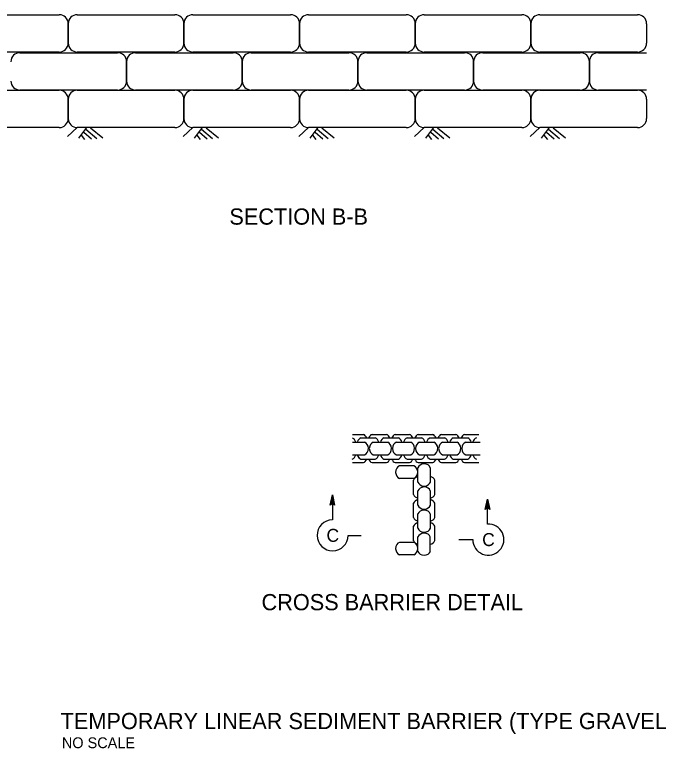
# Model space of a CAD drawing. Extents: x 6707406 to 6714471, y 1868570 to 1872341.
# Drawn here: x 6712375.3 to 6712732.5, y 1869412.9 to 1869820.3 of the extents above; entities that cross this region are included whole.
import ezdxf

# ---------------------------------------------------------------- set-up
doc = ezdxf.new("R2010")
doc.units = 0
for name, color, linetype in [('56 Stg 3 Anno', 7, 'Continuous'), ('57 Undefined', 7, 'Continuous'), ('59 Soundwall Ann', 7, 'Continuous'), ('C - SANDBAG', 7, 'Continuous'), ('G-SYMB', 7, 'Continuous'), ('G-TEXT', 7, 'Continuous')]:
    doc.layers.add(name, color=color, linetype=linetype)

msp = doc.modelspace()

# ---------------------------------------------------------------- linework, layer by layer
at = {"layer": '56 Stg 3 Anno'}
for p, q in [((6712550.31, 1869547.91), (6712551.6, 1869553.67)), ((6712551.6, 1869553.67), (6712551.6, 1869553.67)), ((6712551.6, 1869553.67), (6712552.88, 1869547.91)), ((6712551.6, 1869553.67), (6712551.6, 1869539.74)), ((6712550.65, 1869548.11), (6712551.6, 1869552.35)), ((6712551, 1869548.34), (6712551.6, 1869551.02)), ((6712551.33, 1869548.51), (6712551.6, 1869549.69)), ((6712551.6, 1869552.33), (6712552.53, 1869548.13)), ((6712551.6, 1869551.02), (6712552.2, 1869548.3)), ((6712551.6, 1869549.69), (6712551.85, 1869548.53)), ((6712636.34, 1869545.55), (6712637.62, 1869551.31)), ((6712636.68, 1869545.76), (6712637.62, 1869549.99)), ((6712637.62, 1869551.31), (6712637.62, 1869551.31)), ((6712637.62, 1869551.31), (6712638.9, 1869545.55)), ((6712637.62, 1869537.38), (6712637.62, 1869551.31)), ((6712637.63, 1869549.98), (6712638.56, 1869545.78)), ((6712551.6, 1869548.68), (6712550.31, 1869547.91)), ((6712550.31, 1869547.91), (6712550.31, 1869547.91)), ((6712552.88, 1869547.91), (6712551.6, 1869548.68)), ((6712552.88, 1869547.91), (6712552.88, 1869547.91)), ((6712637.62, 1869546.32), (6712636.34, 1869545.55)), ((6712636.34, 1869545.55), (6712636.34, 1869545.55)), ((6712637.02, 1869545.98), (6712637.62, 1869548.66)), ((6712637.36, 1869546.15), (6712637.62, 1869547.33)), ((6712637.62, 1869548.66), (6712638.22, 1869545.95)), ((6712637.62, 1869547.33), (6712637.88, 1869546.17)), ((6712638.9, 1869545.55), (6712637.62, 1869546.32)), ((6712638.9, 1869545.55), (6712638.9, 1869545.55)), ((6712560.4, 1869531.11), (6712567.53, 1869531.11)), ((6712621.83, 1869528.76), (6712629.56, 1869528.76))]:
    msp.add_line(p, q, dxfattribs=at)
for centre, start, end in [((6712551.77, 1869531.12), 91.113, 359.9585), ((6712638.15, 1869528.77), 180.1055, 93.4975)]:
    msp.add_arc(centre, 8.62, start, end, dxfattribs=at)
at = {"layer": '59 Soundwall Ann'}
for p, q in [((6712410.04, 1869757.57), (6712404.56, 1869752.69)), ((6712415.24, 1869757.53), (6712410.72, 1869751.78)), ((6712417.34, 1869757.51), (6712424.27, 1869751.81)), ((6712474.23, 1869757.57), (6712468.75, 1869752.69)), ((6712479.42, 1869757.53), (6712474.91, 1869751.78)), ((6712481.53, 1869757.51), (6712488.46, 1869751.81)), ((6712538.42, 1869757.57), (6712532.94, 1869752.69)), ((6712543.61, 1869757.53), (6712539.1, 1869751.78)), ((6712545.72, 1869757.51), (6712552.64, 1869751.81)), ((6712602.61, 1869757.57), (6712597.13, 1869752.69)), ((6712607.8, 1869757.53), (6712603.28, 1869751.78)), ((6712609.91, 1869757.51), (6712616.83, 1869751.81)), ((6712666.79, 1869757.57), (6712661.32, 1869752.69)), ((6712671.99, 1869757.53), (6712667.47, 1869751.78)), ((6712674.1, 1869757.51), (6712681.02, 1869751.81)), ((6712412.16, 1869753.43), (6712414.14, 1869751)), ((6712413.66, 1869755.08), (6712417.89, 1869751.24)), ((6712414.79, 1869756.67), (6712420.98, 1869751.57)), ((6712476.35, 1869753.43), (6712478.33, 1869751)), ((6712477.85, 1869755.08), (6712482.07, 1869751.24)), ((6712478.98, 1869756.67), (6712485.17, 1869751.57)), ((6712540.54, 1869753.43), (6712542.52, 1869751)), ((6712542.04, 1869755.08), (6712546.26, 1869751.24)), ((6712543.17, 1869756.67), (6712549.36, 1869751.57)), ((6712604.72, 1869753.43), (6712606.7, 1869751)), ((6712606.22, 1869755.08), (6712610.45, 1869751.24)), ((6712607.36, 1869756.67), (6712613.55, 1869751.57)), ((6712668.91, 1869753.43), (6712670.89, 1869751)), ((6712670.41, 1869755.08), (6712674.64, 1869751.24)), ((6712671.54, 1869756.67), (6712677.73, 1869751.57))]:
    msp.add_line(p, q, dxfattribs=at)
at = {"layer": 'C - SANDBAG'}
for p, q in [((6712562.77, 1869587.15), (6712568.81, 1869587.15)), ((6712573.63, 1869587.15), (6712581.63, 1869587.15)), ((6712573.63, 1869587.15), (6712581.63, 1869587.15)), ((6712586.45, 1869587.15), (6712594.45, 1869587.15)), ((6712599.27, 1869587.15), (6712607.27, 1869587.15)), ((6712612.09, 1869587.15), (6712620.1, 1869587.15)), ((6712624.91, 1869587.15), (6712632.92, 1869587.15)), ((6712562.77, 1869582.8), (6712569.5, 1869582.8)), ((6712567.43, 1869585.2), (6712575.44, 1869585.2)), ((6712567.43, 1869585.2), (6712575.44, 1869585.2)), ((6712574.32, 1869582.8), (6712582.32, 1869582.8)), ((6712574.32, 1869582.8), (6712582.32, 1869582.8)), ((6712580.25, 1869585.2), (6712588.26, 1869585.2)), ((6712587.14, 1869582.79), (6712595.14, 1869582.79)), ((6712593.07, 1869585.2), (6712601.08, 1869585.2)), ((6712599.96, 1869582.79), (6712607.96, 1869582.79)), ((6712605.9, 1869585.2), (6712613.9, 1869585.2)), ((6712612.78, 1869582.79), (6712620.78, 1869582.79)), ((6712618.72, 1869585.2), (6712626.72, 1869585.2)), ((6712625.6, 1869582.79), (6712633.61, 1869582.79)), ((6712562.77, 1869575.9), (6712569.5, 1869575.9)), ((6712574.32, 1869575.9), (6712582.32, 1869575.9)), ((6712574.32, 1869575.9), (6712582.32, 1869575.9)), ((6712587.14, 1869575.9), (6712595.14, 1869575.9)), ((6712599.96, 1869575.9), (6712607.96, 1869575.9)), ((6712612.78, 1869575.9), (6712620.78, 1869575.9)), ((6712625.6, 1869575.9), (6712633.61, 1869575.9)), ((6712562.77, 1869571.55), (6712568.81, 1869571.55)), ((6712567.43, 1869573.5), (6712575.44, 1869573.5)), ((6712567.43, 1869573.5), (6712575.44, 1869573.5)), ((6712573.63, 1869571.55), (6712581.63, 1869571.55)), ((6712573.63, 1869571.55), (6712581.63, 1869571.55)), ((6712580.25, 1869573.5), (6712588.26, 1869573.5)), ((6712586.45, 1869571.54), (6712594.45, 1869571.54)), ((6712593.07, 1869573.5), (6712601.08, 1869573.5)), ((6712599.27, 1869571.54), (6712607.27, 1869571.54)), ((6712605.9, 1869573.5), (6712613.9, 1869573.5)), ((6712612.09, 1869571.54), (6712620.1, 1869571.54)), ((6712618.72, 1869573.5), (6712626.72, 1869573.5)), ((6712624.91, 1869571.54), (6712632.92, 1869571.54)), ((6712596.84, 1869569.67), (6712588.83, 1869569.67)), ((6712599.08, 1869560.69), (6712599.08, 1869568.7)), ((6712605.98, 1869560.69), (6712605.98, 1869568.7)), ((6712596.84, 1869562.78), (6712588.83, 1869562.78)), ((6712596.68, 1869553.81), (6712596.68, 1869561.82)), ((6712608.38, 1869553.81), (6712608.38, 1869561.82)), ((6712599.08, 1869547.87), (6712599.08, 1869555.88)), ((6712605.98, 1869547.87), (6712605.98, 1869555.88)), ((6712596.68, 1869540.99), (6712596.68, 1869549)), ((6712608.38, 1869540.99), (6712608.38, 1869549)), ((6712599.08, 1869535.05), (6712599.08, 1869543.06)), ((6712605.98, 1869535.05), (6712605.98, 1869543.06)), ((6712596.68, 1869528.17), (6712596.68, 1869536.18)), ((6712608.38, 1869528.17), (6712608.38, 1869536.18)), ((6712599.08, 1869522.23), (6712599.08, 1869530.24)), ((6712599.08, 1869522.23), (6712599.08, 1869530.24)), ((6712605.97, 1869522.23), (6712605.97, 1869530.24)), ((6712605.97, 1869522.23), (6712605.97, 1869530.24)), ((6712596.84, 1869527.24), (6712588.83, 1869527.24)), ((6712596.84, 1869520.35), (6712588.83, 1869520.35))]:
    msp.add_line(p, q, dxfattribs=at)
for centre, major_axis, ratio, start_param, end_param in [((6712568.33, 1869583.47), (0.06, -3.75), 0.71077, 2.038051, 2.935943), ((6712574.15, 1869583.47), (0.06, -3.75), 0.711359, 3.317588, 4.221159), ((6712574.15, 1869583.47), (0.06, -3.75), 0.711359, 3.317588, 4.221159), ((6712581.15, 1869583.47), (0.06, -3.75), 0.71077, 2.038051, 2.935943), ((6712581.15, 1869583.47), (0.06, -3.75), 0.71077, 2.038051, 2.935943), ((6712586.97, 1869583.47), (0.06, -3.75), 0.711359, 3.317588, 4.221159), ((6712593.97, 1869583.47), (0.06, -3.75), 0.71077, 2.038051, 2.935943), ((6712599.79, 1869583.47), (0.06, -3.75), 0.711359, 3.317588, 4.221159), ((6712606.79, 1869583.47), (0.06, -3.75), 0.71077, 2.038051, 2.935943), ((6712612.61, 1869583.47), (0.06, -3.75), 0.711359, 3.317588, 4.221159), ((6712619.61, 1869583.47), (0.06, -3.75), 0.71077, 2.038051, 2.935943), ((6712625.44, 1869583.47), (0.06, -3.75), 0.711359, 3.317588, 4.221159), ((6712562.07, 1869581.53), (0, -3.75), 0.71077, 1.915159, 2.876513), ((6712567.96, 1869581.52), (0.06, -3.75), 0.711359, 3.317588, 4.29466), ((6712567.96, 1869581.52), (0.06, -3.75), 0.711359, 3.317588, 4.29466), ((6712568.96, 1869579.12), (0, -3.75), 0.71077, 1.662213, 2.935943), ((6712574.78, 1869579.1), (0, -3.75), 0.711359, 3.317588, 4.646994), ((6712574.78, 1869579.1), (0, -3.75), 0.711359, 3.317588, 4.646994), ((6712574.9, 1869581.53), (0, -3.75), 0.71077, 1.915159, 2.935943), ((6712574.9, 1869581.53), (0, -3.75), 0.71077, 1.915159, 2.935943), ((6712580.78, 1869581.52), (0.06, -3.75), 0.711359, 3.317588, 4.353284), ((6712581.78, 1869579.12), (0, -3.75), 0.71077, 1.662213, 2.935943), ((6712581.78, 1869579.12), (0, -3.75), 0.71077, 1.662213, 2.935943), ((6712587.6, 1869579.1), (0, -3.75), 0.711359, 3.317588, 4.646994), ((6712587.72, 1869581.53), (0, -3.75), 0.71077, 1.915159, 2.935943), ((6712593.6, 1869581.52), (0.06, -3.75), 0.711359, 3.317588, 4.353284), ((6712594.6, 1869579.12), (0, -3.75), 0.71077, 1.662213, 2.935943), ((6712600.42, 1869579.1), (0, -3.75), 0.711359, 3.317588, 4.646994), ((6712600.54, 1869581.53), (0, -3.75), 0.71077, 1.915159, 2.935943), ((6712606.42, 1869581.52), (0.06, -3.75), 0.711359, 3.317588, 4.353284), ((6712607.42, 1869579.12), (0, -3.75), 0.71077, 1.662213, 2.935943), ((6712613.24, 1869579.1), (0, -3.75), 0.711359, 3.317588, 4.646994), ((6712613.36, 1869581.53), (0, -3.75), 0.71077, 1.915159, 2.935943), ((6712619.24, 1869581.52), (0.06, -3.75), 0.711359, 3.317588, 4.353284), ((6712620.24, 1869579.12), (0, -3.75), 0.71077, 1.662213, 2.935943), ((6712626.07, 1869579.1), (0, -3.75), 0.711359, 3.317588, 4.646994), ((6712626.18, 1869581.53), (0, -3.75), 0.71077, 1.915159, 2.935943), ((6712632.06, 1869581.52), (0.06, -3.75), 0.711359, 3.317588, 4.29466), ((6712568.96, 1869579.58), (0, 3.75), 0.71077, 3.347242, 4.682592), ((6712574.78, 1869579.59), (0, 3.75), 0.711359, 1.636191, 2.965597), ((6712574.78, 1869579.59), (0, 3.75), 0.711359, 1.636191, 2.965597), ((6712581.78, 1869579.58), (0, 3.75), 0.71077, 3.347242, 4.682592), ((6712581.78, 1869579.58), (0, 3.75), 0.71077, 3.347242, 4.682592), ((6712587.6, 1869579.59), (0, 3.75), 0.711359, 1.636191, 2.965597), ((6712594.6, 1869579.58), (0, 3.75), 0.71077, 3.347242, 4.682592), ((6712600.42, 1869579.59), (0, 3.75), 0.711359, 1.636191, 2.965597), ((6712607.42, 1869579.58), (0, 3.75), 0.71077, 3.347242, 4.682592), ((6712613.24, 1869579.59), (0, 3.75), 0.711359, 1.636191, 2.965597), ((6712620.24, 1869579.57), (0, 3.75), 0.71077, 3.347242, 4.682592), ((6712626.07, 1869579.59), (0, 3.75), 0.711359, 1.636191, 2.965597), ((6712562.07, 1869577.17), (0, 3.75), 0.71077, 3.347242, 4.368026), ((6712567.96, 1869577.18), (0.06, 3.75), 0.711359, 1.929645, 2.965597), ((6712567.96, 1869577.18), (0.06, 3.75), 0.711359, 1.988526, 2.965597), ((6712574.9, 1869577.17), (0, 3.75), 0.71077, 3.347242, 4.368026), ((6712574.9, 1869577.17), (0, 3.75), 0.71077, 3.347242, 4.368026), ((6712580.78, 1869577.18), (0.06, 3.75), 0.711359, 1.929645, 2.965597), ((6712587.72, 1869577.17), (0, 3.75), 0.71077, 3.347242, 4.368026), ((6712593.6, 1869577.18), (0.06, 3.75), 0.711359, 1.929645, 2.965597), ((6712600.54, 1869577.17), (0, 3.75), 0.71077, 3.347242, 4.368026), ((6712606.42, 1869577.18), (0.06, 3.75), 0.711359, 1.929645, 2.965597), ((6712613.36, 1869577.17), (0, 3.75), 0.71077, 3.347242, 4.368026), ((6712619.24, 1869577.18), (0.06, 3.75), 0.711359, 1.929645, 2.965597), ((6712626.18, 1869577.17), (0, 3.75), 0.71077, 3.347242, 4.368026), ((6712632.06, 1869577.18), (0.06, 3.75), 0.711359, 1.929645, 2.965597), ((6712568.33, 1869575.23), (0.06, 3.75), 0.71077, 3.347242, 4.244863), ((6712574.15, 1869575.23), (0.06, 3.75), 0.711359, 2.062027, 2.965597), ((6712574.15, 1869575.23), (0.06, 3.75), 0.711359, 2.062027, 2.965597), ((6712581.15, 1869575.23), (0.06, 3.75), 0.71077, 3.347242, 4.244863), ((6712581.15, 1869575.23), (0.06, 3.75), 0.71077, 3.347242, 4.244863), ((6712586.97, 1869575.23), (0.06, 3.75), 0.711359, 2.062027, 2.965597), ((6712593.97, 1869575.23), (0.06, 3.75), 0.71077, 3.347242, 4.244863), ((6712599.79, 1869575.23), (0.06, 3.75), 0.711359, 2.062027, 2.965597), ((6712602.76, 1869568.16), (3.75, 0), 0.71077, 1.662213, 2.935943), ((6712602.3, 1869568.16), (-3.75, 0), 0.71077, 3.347242, 4.682592), ((6712606.79, 1869575.23), (0.06, 3.75), 0.71077, 3.347242, 4.244863), ((6712612.61, 1869575.23), (0.06, 3.75), 0.711359, 2.062027, 2.965597), ((6712619.61, 1869575.22), (0.06, 3.75), 0.71077, 3.347242, 4.244863), ((6712625.44, 1869575.23), (0.06, 3.75), 0.711359, 2.062027, 2.965597), ((6712589.37, 1869566), (0, -3.75), 0.71077, 3.347242, 4.682592), ((6712589.37, 1869566.45), (0, 3.75), 0.71077, 1.662213, 2.935943), ((6712596.37, 1869565.98), (0, -3.75), 0.711359, 1.636191, 2.965597), ((6712596.37, 1869566.47), (0, 3.75), 0.711359, 3.317588, 4.646994), ((6712600.35, 1869561.27), (3.75, 0), 0.71077, 1.915159, 2.935943), ((6712604.71, 1869561.27), (-3.75, 0), 0.71077, 3.347242, 4.368026), ((6712602.78, 1869561.16), (3.75, 0), 0.711359, 3.317588, 4.646994), ((6712602.76, 1869555.33), (3.75, 0), 0.71077, 1.662213, 2.935943), ((6712602.3, 1869555.33), (-3.75, 0), 0.71077, 3.347242, 4.682592), ((6712602.29, 1869561.16), (-3.75, 0), 0.711359, 1.636191, 2.965597), ((6712600.36, 1869554.34), (3.75, 0.06), 0.711359, 3.317588, 4.353284), ((6712604.7, 1869554.34), (-3.75, 0.06), 0.711359, 1.929645, 2.965597), ((6712600.35, 1869548.45), (3.75, 0), 0.71077, 1.915159, 2.935943), ((6712604.71, 1869548.45), (-3.75, 0), 0.71077, 3.347242, 4.368026), ((6712602.78, 1869548.34), (3.75, 0), 0.711359, 3.317588, 4.646994), ((6712602.29, 1869548.34), (-3.75, 0), 0.711359, 1.636191, 2.965597), ((6712602.76, 1869542.51), (3.75, 0), 0.71077, 1.662213, 2.935943), ((6712602.3, 1869542.51), (-3.75, 0), 0.71077, 3.347242, 4.682592), ((6712600.36, 1869541.52), (3.75, 0.06), 0.711359, 3.317588, 4.353284), ((6712600.35, 1869535.63), (3.75, 0), 0.71077, 1.915159, 2.935943), ((6712604.7, 1869541.52), (-3.75, 0.06), 0.711359, 1.929645, 2.965597), ((6712604.71, 1869535.63), (-3.75, 0), 0.71077, 3.347242, 4.368026), ((6712602.77, 1869535.52), (3.75, 0), 0.711359, 3.317588, 4.646994), ((6712602.28, 1869535.52), (-3.75, 0), 0.711359, 1.636191, 2.965597), ((6712602.76, 1869529.69), (3.75, 0), 0.71077, 1.662213, 2.935943), ((6712602.76, 1869529.69), (3.75, 0), 0.71077, 1.662213, 2.935943), ((6712602.3, 1869529.69), (-3.75, 0), 0.71077, 3.347242, 4.682592), ((6712602.3, 1869529.69), (-3.75, 0), 0.71077, 3.347242, 4.682592), ((6712589.37, 1869523.57), (0, -3.75), 0.71077, 3.347242, 4.682592), ((6712600.36, 1869528.7), (3.75, 0.06), 0.711359, 3.317588, 4.353284), ((6712596.37, 1869523.55), (0, -3.75), 0.711359, 1.636191, 2.965597), ((6712604.7, 1869528.7), (-3.75, 0.06), 0.711359, 1.929645, 2.965597), ((6712589.37, 1869524.02), (0, 3.75), 0.71077, 1.662213, 2.935943), ((6712596.37, 1869524.04), (0, 3.75), 0.711359, 3.317588, 4.646994), ((6712602.77, 1869522.7), (3.75, 0), 0.711359, 3.317588, 4.646994), ((6712602.28, 1869522.7), (-3.75, 0), 0.711359, 1.636191, 2.965597)]:
    msp.add_ellipse(centre, major_axis=major_axis, ratio=ratio, start_param=start_param, end_param=end_param, dxfattribs=at)
at = {"layer": 'G-SYMB'}
for p, q in [((6712345.85, 1869820.27), (6712400.04, 1869820.27)), ((6712410.04, 1869820.27), (6712464.23, 1869820.27)), ((6712474.23, 1869820.27), (6712528.42, 1869820.27)), ((6712538.42, 1869820.27), (6712592.61, 1869820.27)), ((6712602.61, 1869820.27), (6712656.79, 1869820.27)), ((6712666.79, 1869820.27), (6712720.98, 1869820.27)), ((6712405.04, 1869815.27), (6712405.04, 1869804.54)), ((6712405.04, 1869804.54), (6712405.04, 1869815.27)), ((6712469.23, 1869815.27), (6712469.23, 1869804.54)), ((6712469.23, 1869804.54), (6712469.23, 1869815.27)), ((6712533.42, 1869815.27), (6712533.42, 1869804.54)), ((6712533.42, 1869804.54), (6712533.42, 1869815.27)), ((6712597.61, 1869815.27), (6712597.61, 1869804.54)), ((6712597.61, 1869804.54), (6712597.61, 1869815.27)), ((6712661.79, 1869815.27), (6712661.79, 1869804.54)), ((6712661.79, 1869815.27), (6712661.79, 1869804.54)), ((6712661.79, 1869804.54), (6712661.79, 1869815.27)), ((6712725.98, 1869815.27), (6712725.98, 1869804.54)), ((6712400.04, 1869799.54), (6712345.85, 1869799.54)), ((6712378.26, 1869799.17), (6712432.44, 1869799.17)), ((6712464.23, 1869799.54), (6712410.04, 1869799.54)), ((6712442.44, 1869799.17), (6712496.63, 1869799.17)), ((6712528.42, 1869799.54), (6712474.23, 1869799.54)), ((6712506.63, 1869799.17), (6712560.82, 1869799.17)), ((6712592.61, 1869799.54), (6712538.42, 1869799.54)), ((6712570.82, 1869799.17), (6712625.01, 1869799.17)), ((6712656.79, 1869799.54), (6712602.61, 1869799.54)), ((6712635.01, 1869799.17), (6712689.2, 1869799.17)), ((6712720.98, 1869799.54), (6712666.79, 1869799.54)), ((6712699.2, 1869799.17), (6712725.98, 1869799.17)), ((6712437.44, 1869794.17), (6712437.44, 1869783.43)), ((6712437.44, 1869783.43), (6712437.44, 1869794.17)), ((6712437.44, 1869783.43), (6712437.44, 1869794.17)), ((6712501.63, 1869794.17), (6712501.63, 1869783.43)), ((6712501.63, 1869783.43), (6712501.63, 1869794.17)), ((6712501.63, 1869783.43), (6712501.63, 1869794.17)), ((6712565.82, 1869794.17), (6712565.82, 1869783.43)), ((6712565.82, 1869783.43), (6712565.82, 1869794.17)), ((6712565.82, 1869783.43), (6712565.82, 1869794.17)), ((6712630.01, 1869794.17), (6712630.01, 1869783.43)), ((6712630.01, 1869783.43), (6712630.01, 1869794.17)), ((6712630.01, 1869783.43), (6712630.01, 1869794.17)), ((6712694.2, 1869794.17), (6712694.2, 1869783.43)), ((6712694.2, 1869783.43), (6712694.2, 1869794.17)), ((6712694.2, 1869783.43), (6712694.2, 1869794.17)), ((6712345.85, 1869778.31), (6712400.04, 1869778.31)), ((6712432.44, 1869778.43), (6712378.26, 1869778.43)), ((6712410.04, 1869778.31), (6712464.23, 1869778.31)), ((6712496.63, 1869778.43), (6712442.44, 1869778.43)), ((6712474.23, 1869778.31), (6712528.42, 1869778.31)), ((6712560.82, 1869778.43), (6712506.63, 1869778.43)), ((6712538.42, 1869778.31), (6712592.61, 1869778.31)), ((6712625.01, 1869778.43), (6712570.82, 1869778.43)), ((6712602.61, 1869778.31), (6712656.79, 1869778.31)), ((6712689.2, 1869778.43), (6712635.01, 1869778.43)), ((6712666.79, 1869778.31), (6712720.98, 1869778.31)), ((6712725.98, 1869778.43), (6712699.2, 1869778.43)), ((6712405.04, 1869773.31), (6712405.04, 1869762.57)), ((6712405.04, 1869762.57), (6712405.04, 1869773.31)), ((6712469.23, 1869773.31), (6712469.23, 1869762.57)), ((6712469.23, 1869762.57), (6712469.23, 1869773.31)), ((6712533.42, 1869773.31), (6712533.42, 1869762.57)), ((6712533.42, 1869762.57), (6712533.42, 1869773.31)), ((6712597.61, 1869773.31), (6712597.61, 1869762.57)), ((6712597.61, 1869762.57), (6712597.61, 1869773.31)), ((6712661.79, 1869773.31), (6712661.79, 1869762.57)), ((6712661.79, 1869773.31), (6712661.79, 1869762.57)), ((6712661.79, 1869762.57), (6712661.79, 1869773.31)), ((6712725.98, 1869773.31), (6712725.98, 1869762.57)), ((6712400.04, 1869757.57), (6712345.85, 1869757.57)), ((6712464.23, 1869757.57), (6712410.04, 1869757.57)), ((6712528.42, 1869757.57), (6712474.23, 1869757.57)), ((6712592.61, 1869757.57), (6712538.42, 1869757.57)), ((6712656.79, 1869757.57), (6712602.61, 1869757.57)), ((6712720.98, 1869757.57), (6712666.79, 1869757.57))]:
    msp.add_line(p, q, dxfattribs=at)
for centre, start, end in [((6712400.04, 1869815.27), 0, 90), ((6712410.04, 1869815.27), 90, 180), ((6712464.23, 1869815.27), 0, 90), ((6712474.23, 1869815.27), 90, 180), ((6712528.42, 1869815.27), 0, 90), ((6712538.42, 1869815.27), 90, 180), ((6712592.61, 1869815.27), 0, 90), ((6712602.61, 1869815.27), 90, 180), ((6712656.79, 1869815.27), 0, 90), ((6712666.79, 1869815.27), 90, 180), ((6712720.98, 1869815.27), 0, 90), ((6712400.04, 1869804.54), 270, 0), ((6712410.04, 1869804.54), 180, 270), ((6712464.23, 1869804.54), 270, 0), ((6712474.23, 1869804.54), 180, 270), ((6712528.42, 1869804.54), 270, 0), ((6712538.42, 1869804.54), 180, 270), ((6712592.61, 1869804.54), 270, 0), ((6712602.61, 1869804.54), 180, 270), ((6712656.79, 1869804.54), 270, 0), ((6712666.79, 1869804.54), 180, 270), ((6712720.98, 1869804.54), 270, 0), ((6712378.26, 1869794.17), 90, 180), ((6712432.44, 1869794.17), 0, 90), ((6712442.44, 1869794.17), 90, 180), ((6712496.63, 1869794.17), 0, 90), ((6712506.63, 1869794.17), 90, 180), ((6712560.82, 1869794.17), 0, 90), ((6712570.82, 1869794.17), 90, 180), ((6712625.01, 1869794.17), 0, 90), ((6712635.01, 1869794.17), 90, 180), ((6712689.2, 1869794.17), 0, 90), ((6712699.2, 1869794.17), 90, 180), ((6712378.26, 1869783.43), 180, 270), ((6712432.44, 1869783.43), 270, 0), ((6712442.44, 1869783.43), 180, 270), ((6712496.63, 1869783.43), 270, 0), ((6712506.63, 1869783.43), 180, 270), ((6712560.82, 1869783.43), 270, 0), ((6712570.82, 1869783.43), 180, 270), ((6712625.01, 1869783.43), 270, 0), ((6712635.01, 1869783.43), 180, 270), ((6712689.2, 1869783.43), 270, 0), ((6712699.2, 1869783.43), 180, 270), ((6712400.04, 1869773.31), 0, 90), ((6712410.04, 1869773.31), 90, 180), ((6712464.23, 1869773.31), 0, 90), ((6712474.23, 1869773.31), 90, 180), ((6712528.42, 1869773.31), 0, 90), ((6712538.42, 1869773.31), 90, 180), ((6712592.61, 1869773.31), 0, 90), ((6712602.61, 1869773.31), 90, 180), ((6712656.79, 1869773.31), 0, 90), ((6712666.79, 1869773.31), 90, 180), ((6712720.98, 1869773.31), 0, 90), ((6712400.04, 1869762.57), 270, 0), ((6712410.04, 1869762.57), 180, 270), ((6712464.23, 1869762.57), 270, 0), ((6712474.23, 1869762.57), 180, 270), ((6712528.42, 1869762.57), 270, 0), ((6712538.42, 1869762.57), 180, 270), ((6712592.61, 1869762.57), 270, 0), ((6712602.61, 1869762.57), 180, 270), ((6712656.79, 1869762.57), 270, 0), ((6712666.79, 1869762.57), 180, 270), ((6712720.98, 1869762.57), 270, 0)]:
    msp.add_arc(centre, 5, start, end, dxfattribs=at)

# ---------------------------------------------------------------- texts
at = {"layer": '57 Undefined'}
for s, height, p in [('SECTION B-B', 9, (6712494.48, 1869703.66)), ('C', 7.21, (6712548.37, 1869527.52)), ('C', 7.21, (6712634.75, 1869525.16)), ('CROSS BARRIER DETAIL', 9, (6712512.32, 1869489.53)), ('TEMPORARY LINEAR SEDIMENT BARRIER (TYPE GRAVEL BAG BERM)', 9, (6712400.85, 1869423.52))]:
    msp.add_text(s, height=height, dxfattribs=at).set_placement(p)
at = {"layer": 'G-TEXT'}
msp.add_text('NO SCALE', height=6, rotation=360, dxfattribs=at).set_placement((6712401.53, 1869412.94))

doc.saveas('drawing.dxf')
